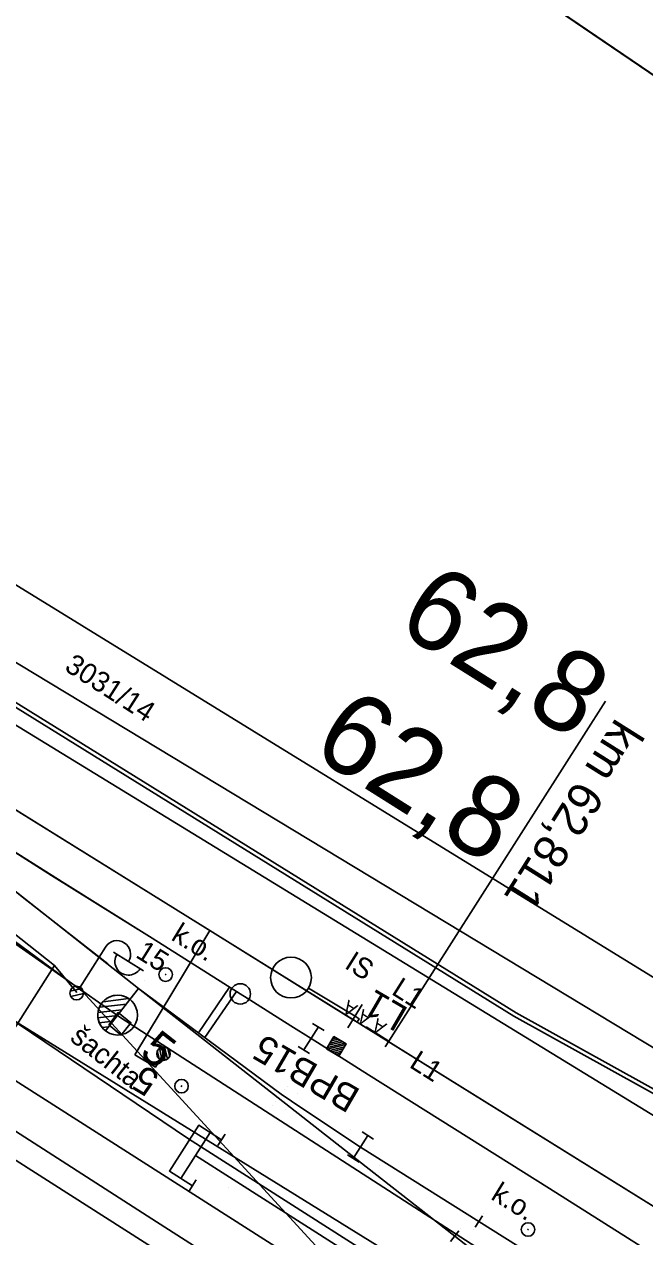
# Model space of a CAD drawing. Extents: x -621145 to -620023, y -1122866 to -1121971.
# Drawn here: x -620819.8 to -620774.1, y -1122375 to -1122285.8 of the extents above; entities that cross this region are included whole.
import ezdxf

# ---------------------------------------------------------------- set-up
doc = ezdxf.new("R2010")
doc.units = 0
for name, color, linetype in [('060601_EOV', 7, 'Continuous'), ('060604_ROZVODY_SEE', 7, 'Continuous'), ('CETIN', 7, 'Continuous'), ('PS 06-14-01_trasa_sdělovací_nové', 7, 'Continuous'), ('RÁMY', 7, 'Continuous'), ('SEE', 7, 'Continuous'), ('SSZT', 7, 'Continuous'), ('SSZT-DK', 7, 'Continuous'), ('UZEMNĚNÍ', 7, 'Continuous'), ('Vrstva 1', 7, 'Continuous'), ('Vrstva 15', 7, 'Continuous'), ('Vrstva 2', 7, 'Continuous'), ('Vrstva 25', 7, 'Continuous'), ('Vrstva 27', 7, 'Continuous'), ('Vrstva 3', 7, 'Continuous'), ('Vrstva 47', 7, 'Continuous'), ('Vrstva 53', 7, 'Continuous'), ('Vrstva 55', 7, 'Continuous'), ('Vrstva 56', 7, 'Continuous'), ('Vrstva 57', 7, 'Continuous'), ('Vrstva 6', 7, 'Continuous'), ('Vrstva 62', 7, 'Continuous'), ('Vrstva 7', 7, 'Continuous'), ('ČD-T', 7, 'Continuous')]:
    doc.layers.add(name, color=color, linetype=linetype)

msp = doc.modelspace()

# ---------------------------------------------------------------- linework, layer by layer
at = {"layer": '060601_EOV'}
msp.add_lwpolyline([(-620538.89, -1122521.208), (-620599.215, -1122483.216), (-620683.524, -1122429.444), (-620756.33, -1122383.523), (-620765.796, -1122398.395), (-620784.65, -1122386.386), (-620822.218, -1122362.419), (-620817.53, -1122355.085), (-620826.407, -1122348.082), (-620839.916, -1122337.943), (-620848.842, -1122331.997), (-620848.834, -1122331.986)], dxfattribs=at)
at = {"layer": '060604_ROZVODY_SEE'}
msp.add_line((-620815.893, -1122357.078), (-620817.53, -1122355.085), dxfattribs=at)
msp.add_lwpolyline([(-620742.353, -1122414.851), (-620741.729, -1122413.876), (-620750.529, -1122408.246), (-620763.558, -1122399.82), (-620784.65, -1122386.386), (-620822.218, -1122362.419), (-620817.53, -1122355.085), (-620826.407, -1122348.082), (-620839.916, -1122337.943), (-620854.567, -1122328.184), (-620868.06, -1122319.694), (-620885.37, -1122308.815), (-620912.868, -1122291.527), (-620913.325, -1122292.255)], dxfattribs=at)
at = {"layer": 'CETIN'}
msp.add_lwpolyline([(-620926.411, -1122268.704), (-620748.436, -1122376.269), (-620484.52, -1122538.147)], dxfattribs=at)
at = {"layer": 'PS 06-14-01_trasa_sdělovací_nové'}
msp.add_lwpolyline([(-620756.33, -1122383.523), (-620759.752, -1122381.362), (-620756.353, -1122375.206), (-620764.724, -1122371.2), (-620767.847, -1122376.3), (-620853.066, -1122323.342), (-620895.691, -1122296.632), (-620912.11, -1122286.226), (-620914.885, -1122290.617), (-620933.415, -1122279.017)], dxfattribs=at)
at = {"layer": 'RÁMY'}
for points in [[(-621061.558, -1122093.918), (-620106.075, -1122742.822), (-620189.505, -1122865.67), (-621144.989, -1122216.766)], [(-620717.541, -1122148.044), (-620630.679, -1122207.035), (-620714.11, -1122329.883), (-620800.972, -1122270.892)], [(-620887.834, -1122211.901), (-620106.075, -1122742.822), (-620189.505, -1122865.67), (-620971.264, -1122334.748)]]:
    msp.add_lwpolyline(points, close=True, dxfattribs=at)
at = {"layer": 'SEE'}
msp.add_lwpolyline([(-620545.407, -1122539.454), (-620611.375, -1122497.696), (-620665.569, -1122462.755), (-620686.035, -1122449.829), (-620727.537, -1122423.183), (-620794.508, -1122379.862), (-620815.52, -1122356.954), (-620832.168, -1122344.663), (-620847.808, -1122332.592), (-620908.257, -1122294.686)], dxfattribs=at)
at = {"layer": 'SSZT'}
msp.add_lwpolyline([(-620879.238, -1122313.316), (-620842.993, -1122336.61), (-620835.049, -1122343.251), (-620812.66, -1122358.949), (-620764.902, -1122389.752), (-620688.594, -1122438.969), (-620596.981, -1122496.725), (-620576.744, -1122509.484), (-620506.746, -1122556.123), (-620447.293, -1122593.619), (-620363.271, -1122647.563), (-620313.966, -1122679.218), (-620306.51, -1122669.289), (-620273.137, -1122696.274), (-620258.422, -1122709.142), (-620248.072, -1122696.094)], dxfattribs=at)
at = {"layer": 'SSZT-DK'}
msp.add_lwpolyline([(-620927.288, -1122269.995), (-620900.269, -1122286.467), (-620889.147, -1122293.455), (-620783.743, -1122358.818), (-620712.751, -1122398.176), (-620653.117, -1122435.232), (-620617.363, -1122456.738), (-620574.425, -1122482.604)], dxfattribs=at)
at = {"layer": 'UZEMNĚNÍ'}
msp.add_line((-620815.893, -1122357.078), (-620817.53, -1122355.085), dxfattribs=at)
msp.add_lwpolyline([(-620742.353, -1122414.851), (-620741.729, -1122413.876), (-620750.529, -1122408.246), (-620763.558, -1122399.82), (-620784.65, -1122386.386), (-620822.218, -1122362.419), (-620817.53, -1122355.085), (-620826.407, -1122348.082), (-620838.671, -1122338.878), (-620840.227, -1122340.951)], dxfattribs=at)
at = {"layer": 'Vrstva 1'}
for p, q in [((-620806.105, -1122352.525), (-620848.094, -1122326.432)), ((-620811.617, -1122361.655), (-620806.105, -1122352.525))]:
    msp.add_line(p, q, dxfattribs=at)
for points in [[(-620931.811, -1122276.656), (-620929.02, -1122278.418), (-620921.28, -1122283.303), (-620914.453, -1122287.577), (-620907.377, -1122292.038), (-620900.381, -1122296.431), (-620893.375, -1122300.832), (-620887.007, -1122304.836), (-620881.072, -1122308.561), (-620874.799, -1122312.504), (-620868.326, -1122316.573), (-620865.133, -1122318.582), (-620858.377, -1122322.838), (-620854.485, -1122325.283), (-620853.208, -1122326.085), (-620851.733, -1122327.008), (-620850.549, -1122327.758), (-620840.578, -1122334.049), (-620833.632, -1122338.433), (-620832.14, -1122339.366), (-620823.776, -1122344.632), (-620817.743, -1122348.457), (-620811.366, -1122352.452)], [(-620853.345, -1122326.031), (-620853.187, -1122326.13), (-620851.644, -1122327.076), (-620843.142, -1122332.434), (-620837.627, -1122335.918), (-620832.116, -1122339.39), (-620828.016, -1122341.966), (-620823.788, -1122344.633), (-620816.971, -1122348.943), (-620810.355, -1122353.089), (-620803.86, -1122357.181), (-620803.36, -1122357.495), (-620800.131, -1122359.525), (-620798.65, -1122360.458), (-620794.421, -1122363.123), (-620788.102, -1122367.105), (-620781.123, -1122371.499), (-620774.168, -1122375.876)], [(-620851.644, -1122327.076), (-620840.376, -1122334.591), (-620831.192, -1122341.263), (-620824.896, -1122346.12), (-620811.348, -1122356.777), (-620800.849, -1122364.554), (-620800.095, -1122365.072), (-620796.174, -1122367.693), (-620795.017, -1122368.443), (-620786.31, -1122373.928), (-620764.415, -1122387.671), (-620747.632, -1122398.188), (-620733.731, -1122406.893), (-620718.349, -1122416.524), (-620703.006, -1122426.145), (-620686.977, -1122436.203), (-620670.849, -1122446.339), (-620652.243, -1122458.025), (-620632.992, -1122470.125), (-620616.992, -1122480.169), (-620599.707, -1122491.044), (-620582.331, -1122501.971), (-620566.971, -1122511.728)], [(-620851.644, -1122327.076), (-620843.142, -1122332.434), (-620837.627, -1122335.918), (-620832.116, -1122339.39), (-620828.016, -1122341.966), (-620823.788, -1122344.633), (-620816.971, -1122348.943), (-620810.355, -1122353.089), (-620803.86, -1122357.181), (-620803.36, -1122357.495), (-620800.131, -1122359.525), (-620798.65, -1122360.458), (-620794.421, -1122363.123), (-620788.102, -1122367.105), (-620781.123, -1122371.499), (-620774.168, -1122375.876), (-620767.514, -1122380.058), (-620763.223, -1122382.761), (-620756.392, -1122387.049), (-620748.87, -1122391.776), (-620741.59, -1122396.353), (-620734.607, -1122400.749), (-620727.792, -1122405.031)], [(-620850.549, -1122327.758), (-620838.472, -1122335.901), (-620831.257, -1122341.177), (-620824.882, -1122346.101), (-620819.561, -1122350.304), (-620813.61, -1122354.966)], [(-620795.273, -1122359.257), (-620795.675, -1122359.007), (-620806.105, -1122352.525)], [(-620811.348, -1122356.777), (-620801.076, -1122364.818), (-620794.028, -1122370.353), (-620788.085, -1122375.002), (-620768.881, -1122390.097), (-620768.433, -1122390.449), (-620761.754, -1122395.699), (-620755.252, -1122400.953), (-620748.862, -1122405.846), (-620748.158, -1122406.325), (-620737.324, -1122413.726), (-620723.134, -1122422.771)], [(-620795.422, -1122358.821), (-620795.117, -1122359.006), (-620795.273, -1122359.257)], [(-620764.724, -1122371.2), (-620767.847, -1122376.3), (-620794.599, -1122359.676), (-620795.273, -1122359.257)], [(-620809.512, -1122361.576), (-620810.11, -1122362.565), (-620811.617, -1122361.655)], [(-620807.154, -1122369.064), (-620804.382, -1122370.836), (-620783.306, -1122384.278), (-620762.208, -1122397.716), (-620749.177, -1122406.143), (-620748.333, -1122406.684), (-620737.324, -1122413.726)]]:
    msp.add_lwpolyline(points, dxfattribs=at)
at = {"layer": 'Vrstva 15'}
for p, q in [((-620808.231, -1122370.749), (-620806.077, -1122367.379)), ((-620805.504, -1122368.339), (-620804.965, -1122367.496)), ((-620807.658, -1122371.709), (-620807.119, -1122370.866))]:
    msp.add_line(p, q, dxfattribs=at)
msp.add_lwpolyline([(-620805.234, -1122367.917), (-620806.919, -1122366.84), (-620809.074, -1122370.211), (-620807.389, -1122371.288)], dxfattribs=at)
at = {"layer": 'Vrstva 2'}
for p, q in [((-620811.982, -1122357.587), (-620811.348, -1122356.777)), ((-620798.847, -1122356.755), (-620795.422, -1122358.821)), ((-620812.074, -1122357.526), (-620813.959, -1122357.755)), ((-620813.787, -1122359.892), (-620811.982, -1122357.587)), ((-620812.569, -1122358.341), (-620814.332, -1122358.556)), ((-620812.897, -1122358.759), (-620814.33, -1122358.933)), ((-620812.242, -1122357.924), (-620814.226, -1122358.165)), ((-620795.938, -1122359.677), (-620794.905, -1122357.964)), ((-620813.223, -1122359.176), (-620814.231, -1122359.299)), ((-620813.551, -1122359.594), (-620814.024, -1122359.652)), ((-620796.652, -1122360.509), (-620797.16, -1122360.634)), ((-620796.811, -1122360.413), (-620797.064, -1122360.476)), ((-620809.973, -1122361.382), (-620809.829, -1122361.961)), ((-620809.816, -1122361.18), (-620809.597, -1122362.068)), ((-620809.632, -1122361.091), (-620809.393, -1122362.059)), ((-620809.428, -1122361.085), (-620809.209, -1122361.971)), ((-620809.196, -1122361.191), (-620809.053, -1122361.768)), ((-620796.102, -1122360.913), (-620797.458, -1122361.249)), ((-620796.175, -1122360.796), (-620797.448, -1122361.111)), ((-620796.334, -1122360.7), (-620797.352, -1122360.952)), ((-620796.198, -1122361.072), (-620797.299, -1122361.345)), ((-620796.493, -1122360.604), (-620797.256, -1122360.793)), ((-620796.294, -1122361.231), (-620797.14, -1122361.441)), ((-620796.39, -1122361.39), (-620796.981, -1122361.536)), ((-620796.486, -1122361.549), (-620796.822, -1122361.632)), ((-620796.582, -1122361.708), (-620796.663, -1122361.728)), ((-620786.044, -1122373.505), (-620786.576, -1122374.351)), ((-620787.776, -1122374.609), (-620788.394, -1122375.395))]:
    msp.add_line(p, q, dxfattribs=at)
for points in [[(-620811.348, -1122356.777), (-620800.849, -1122364.554), (-620800.095, -1122365.072), (-620796.174, -1122367.693), (-620795.017, -1122368.443), (-620786.31, -1122373.928)], [(-620811.348, -1122356.777), (-620801.076, -1122364.818), (-620794.028, -1122370.353), (-620788.085, -1122375.002)]]:
    msp.add_lwpolyline(points, dxfattribs=at)
msp.add_lwpolyline([(-620796.612, -1122361.759), (-620797.511, -1122361.216), (-620796.969, -1122360.317), (-620796.07, -1122360.86)], close=True, dxfattribs=at)
msp.add_lwpolyline([(-620796.612, -1122361.759), (-620797.511, -1122361.216), (-620796.969, -1122360.317), (-620796.07, -1122360.86)], close=True, dxfattribs=at)
for centre, radius in [((-620800.131, -1122355.98), 1.5), ((-620812.884, -1122358.74), 1.464), ((-620809.512, -1122361.576), 0.5)]:
    msp.add_circle(centre, radius, dxfattribs=at)
msp.add_arc((-620812.884, -1122358.74), 1.463, 51.96502, 231.92587, dxfattribs=at)
at = {"layer": 'Vrstva 25'}
for p, q in [((-620815.635, -1122356.695), (-620813.777, -1122353.73)), ((-620813.184, -1122354.101), (-620810.981, -1122355.482)), ((-620816.384, -1122356.989), (-620815.526, -1122356.792)), ((-620816.336, -1122357.362), (-620815.402, -1122357.148))]:
    msp.add_line(p, q, dxfattribs=at)
msp.add_circle((-620815.901, -1122357.119), 0.5, dxfattribs=at)
for centre, start, end in [((-620812.93, -1122354.261), 327.92616, 147.92616), ((-620812.089, -1122354.802), 147.22359, 328.62874)]:
    msp.add_arc(centre, 1, start, end, dxfattribs=at)
at = {"layer": 'Vrstva 27'}
for p, q in [((-620809.397, -1122355.73), (-620809.311, -1122355.782)), ((-620782.736, -1122374.485), (-620782.65, -1122374.537))]:
    msp.add_line(p, q, dxfattribs=at)
for centre in [(-620809.354, -1122355.756), (-620782.693, -1122374.511)]:
    msp.add_circle(centre, 0.5, dxfattribs=at)
at = {"layer": 'Vrstva 3'}
for p, q in [((-620798.117, -1122359.612), (-620799.183, -1122361.304)), ((-620798.117, -1122359.612), (-620799.183, -1122361.304)), ((-620798.54, -1122359.345), (-620797.694, -1122359.879)), ((-620798.54, -1122359.345), (-620797.694, -1122359.878)), ((-620799.606, -1122361.037), (-620798.76, -1122361.571)), ((-620799.606, -1122361.038), (-620798.76, -1122361.571)), ((-620794.484, -1122367.597), (-620795.55, -1122369.289)), ((-620794.907, -1122367.33), (-620794.061, -1122367.863)), ((-620795.973, -1122369.023), (-620795.127, -1122369.556))]:
    msp.add_line(p, q, dxfattribs=at)
at = {"layer": 'Vrstva 47'}
msp.add_lwpolyline([(-620813.538, -1122359.464), (-620812.851, -1122358.551), (-620811.904, -1122359.301), (-620812.62, -1122360.204), (-620813.538, -1122359.464)], dxfattribs=at)
at = {"layer": 'Vrstva 53'}
for p, q in [((-620838.83, -1122326.12), (-620768.63, -1122369.09)), ((-620741.46, -1122408.09), (-620821.12, -1122358.76))]:
    msp.add_line(p, q, dxfattribs=at)
at = {"layer": 'Vrstva 55'}
for p, q in [((-620866.03, -1122298.98), (-620688.16, -1122408.5)), ((-620838.83, -1122326.12), (-620768.63, -1122369.09)), ((-620821.12, -1122358.76), (-620741.46, -1122408.09)), ((-620807.67, -1122367.84), (-620821.12, -1122358.76)), ((-620684.91, -1122455.63), (-620825.92, -1122365.89)), ((-620645.72, -1122471.03), (-620807.67, -1122367.84))]:
    msp.add_line(p, q, dxfattribs=at)
at = {"layer": 'Vrstva 56'}
for p, q in [((-620824.91, -1122364.39), (-620810.36, -1122373.73)), ((-620810.36, -1122373.73), (-620648.08, -1122477.56))]:
    msp.add_line(p, q, dxfattribs=at)
at = {"layer": 'Vrstva 6'}
for p, q in [((-620792.925, -1122360.656), (-620777.003, -1122335.648)), ((-620794.6, -1122359.6), (-620792.925, -1122360.656)), ((-620794.6, -1122359.6), (-620792.925, -1122360.656)), ((-620793.192, -1122361.079), (-620792.658, -1122360.233)), ((-620793.192, -1122361.079), (-620792.658, -1122360.233))]:
    msp.add_line(p, q, dxfattribs=at)
at = {"layer": 'Vrstva 62'}
for p, q in [((-620810.907, -1122356.198), (-620810.907, -1122356.198)), ((-620811.788, -1122357.355), (-620811.788, -1122357.355)), ((-620800.408, -1122364.001), (-620800.408, -1122364.001)), ((-620800.637, -1122364.243), (-620800.637, -1122364.243)), ((-620799.679, -1122364.494), (-620799.679, -1122364.494)), ((-620801.514, -1122365.393), (-620801.514, -1122365.393)), ((-620801.29, -1122365.107), (-620801.29, -1122365.107)), ((-620800.511, -1122365.651), (-620800.511, -1122365.651)), ((-620795.725, -1122367.141), (-620795.725, -1122367.141)), ((-620806.771, -1122368.468), (-620806.771, -1122368.468)), ((-620796.623, -1122368.246), (-620796.623, -1122368.246)), ((-620794.609, -1122367.871), (-620794.609, -1122367.871)), ((-620795.426, -1122369.016), (-620795.426, -1122369.016)), ((-620807.538, -1122369.661), (-620807.538, -1122369.661)), ((-620804.006, -1122370.225), (-620804.006, -1122370.225)), ((-620793.614, -1122369.769), (-620793.614, -1122369.769)), ((-620794.442, -1122370.937), (-620794.442, -1122370.937)), ((-620804.758, -1122371.448), (-620804.758, -1122371.448)), ((-620785.935, -1122373.327), (-620785.935, -1122373.327)), ((-620787.647, -1122374.431), (-620787.647, -1122374.431)), ((-620786.685, -1122374.529), (-620786.685, -1122374.529))]:
    msp.add_line(p, q, dxfattribs=at)
at = {"layer": 'Vrstva 7'}
for p, q in [((-620804.647, -1122356.685), (-620806.942, -1122360.04)), ((-620804.139, -1122357.005), (-620806.46, -1122360.398)), ((-620805.585, -1122358.587), (-620805.585, -1122358.587)), ((-620808.226, -1122363.939), (-620808.142, -1122363.993)), ((-620808.226, -1122363.939), (-620808.142, -1122363.993))]:
    msp.add_line(p, q, dxfattribs=at)
for centre, radius in [((-620803.86, -1122357.181), 0.75), ((-620803.86, -1122357.181), 0.75), ((-620808.184, -1122363.966), 0.5), ((-620808.184, -1122363.966), 0.5)]:
    msp.add_circle(centre, radius, dxfattribs=at)
at = {"layer": 'ČD-T'}
msp.add_lwpolyline([(-620927.12, -1122269.748), (-620900.082, -1122286.233), (-620888.96, -1122293.22), (-620783.556, -1122358.583), (-620712.564, -1122397.941), (-620652.93, -1122434.998), (-620617.176, -1122456.504), (-620574.237, -1122482.37)], dxfattribs=at)

# ---------------------------------------------------------------- texts
at = {"layer": 'Vrstva 2'}
msp.add_text('5', height=2.5, rotation=321.94589, dxfattribs=at).set_placement((-620811.354, -1122361.655))
at = {"layer": 'Vrstva 25'}
msp.add_text('15', height=1.5, rotation=327.92616, dxfattribs=at).set_placement((-620811.637, -1122354.436))
at = {"layer": 'Vrstva 27'}
for p in [(-620809.024, -1122353.158), (-620785.504, -1122372.238)]:
    msp.add_text('k.o.', height=1.5, rotation=328.4879, dxfattribs=at).set_placement(p)
at = {"layer": 'Vrstva 3'}
for s, height, rotation, p in [('IS', 1.5, 327.7899, (-620796.269, -1122355.229)), ('L1', 2, 149.82357, (-620791.406, -1122358.283)), ('BPB15', 2, 149.82357, (-620794.924, -1122364.273)), ('5', 2, 148.87857, (-620809.692, -1122363.108))]:
    msp.add_text(s, height=height, rotation=rotation, dxfattribs=at).set_placement(p)
at = {"layer": 'Vrstva 47'}
msp.add_text('šachta', height=1.5, rotation=321.62167, dxfattribs=at).set_placement((-620816.466, -1122360.548))
at = {"layer": 'Vrstva 57'}
msp.add_text('3031/14', height=1.5, rotation=327.36654, dxfattribs=at).set_placement((-620816.873, -1122333.329))
at = {"layer": 'Vrstva 6'}
for s, height, rotation, p in [('km 62,811', 2.5, 237.78239, (-620776.215, -1122336.799)), ('L1', 1.5, 327.78239, (-620792.815, -1122357.156)), ('  A A A ', 1, 147.78239, (-620792.392, -1122359.81)), ('  A A ', 1, 147.78239, (-620792.392, -1122359.81)), ('L1', 1.5, 327.78239, (-620791.506, -1122362.527))]:
    msp.add_text(s, height=height, rotation=rotation, dxfattribs=at).set_placement(p)
at = {"layer": 'Vrstva 7'}
for rotation, p in [(327.84334, (-620792.544, -1122330.295)), (327.78813, (-620798.799, -1122339.471))]:
    msp.add_text('62,8', height=6, rotation=rotation, dxfattribs=at).set_placement(p)

doc.saveas('drawing.dxf')
